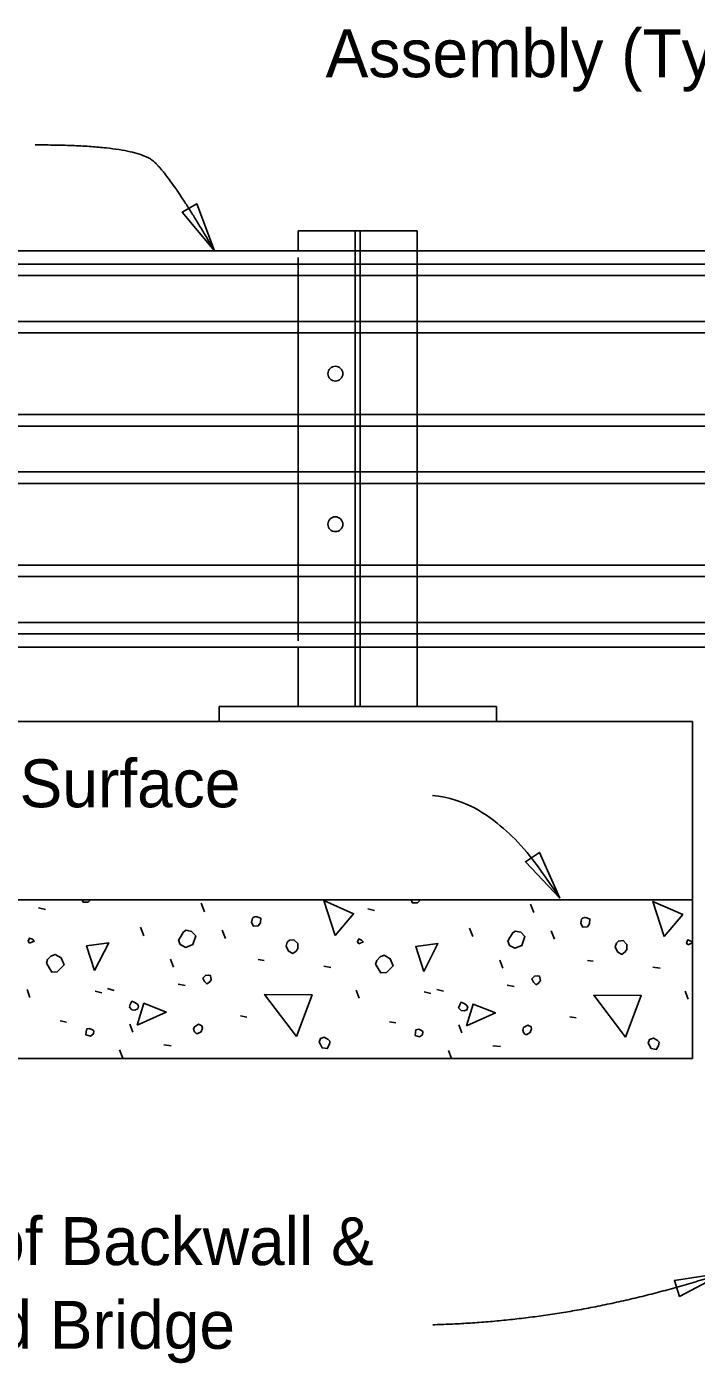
# Model space of a CAD drawing. Extents: x 21587 to 21659.1, y 56116.2 to 56157.3.
# Drawn here: x 21610.68 to 21613.5, y 56132.1 to 56137.72 of the extents above; entities that cross this region are included whole.
import ezdxf

# ---------------------------------------------------------------- set-up
doc = ezdxf.new("R2010")
doc.units = 0
for name, color, linetype in [('AdhocPoint_dp', 7, 'Continuous'), ('Border', 7, 'Continuous'), ('Patterning', 7, 'Continuous'), ('PlotBorder_dp', 7, 'Continuous'), ('SheetBorder_dp', 7, 'Continuous'), ('TextMisc', 7, 'Continuous')]:
    doc.layers.add(name, color=color, linetype=linetype)

msp = doc.modelspace()

# ---------------------------------------------------------------- linework, layer by layer
at = {"layer": 'AdhocPoint_dp'}
for p, q in [((21607.3117, 56134.8009), (21613.4854, 56134.8009)), ((21613.4854, 56134.8008), (21613.4854, 56133.3842)), ((21613.4854, 56134.0509), (21607.3117, 56134.0509)), ((21607.3117, 56133.3843), (21613.4854, 56133.3843))]:
    msp.add_line(p, q, dxfattribs=at)
at = {"layer": 'Border'}
for p, q in [((21611.8268, 56136.8635), (21612.3268, 56136.8635)), ((21611.8268, 56136.8635), (21611.8268, 56136.7802)), ((21612.3268, 56136.8635), (21612.3268, 56136.7802)), ((21619.5663, 56136.7801), (21607.3117, 56136.7801)), ((21607.3117, 56136.7246), (21619.5663, 56136.7246)), ((21607.3117, 56136.6764), (21619.5663, 56136.6764)), ((21607.3117, 56136.4835), (21619.5663, 56136.4835)), ((21607.3117, 56136.4353), (21619.5663, 56136.4353)), ((21607.3117, 56136.0914), (21619.5663, 56136.0914)), ((21607.3117, 56136.0431), (21619.5663, 56136.0431)), ((21607.3117, 56135.8503), (21619.5663, 56135.8503)), ((21607.3117, 56135.8022), (21619.5663, 56135.8022)), ((21607.3117, 56135.4582), (21619.5663, 56135.4582)), ((21607.3117, 56135.41), (21619.5663, 56135.41)), ((21607.3117, 56135.2172), (21619.5663, 56135.2172)), ((21607.3117, 56135.169), (21619.5663, 56135.169)), ((21619.5663, 56135.1134), (21607.3117, 56135.1134)), ((21611.8268, 56135.1135), (21611.8268, 56134.8635)), ((21612.3268, 56135.1134), (21612.3268, 56134.8635)), ((21611.4935, 56134.8635), (21612.6601, 56134.8635)), ((21611.4935, 56134.801), (21611.4935, 56134.8635)), ((21611.8268, 56134.8635), (21612.3268, 56134.8635)), ((21612.6601, 56134.8635), (21612.6601, 56134.801)), ((21611.4935, 56134.801), (21612.6601, 56134.801))]:
    msp.add_line(p, q, dxfattribs=at)
for centre in [(21611.983, 56136.2634), (21611.983, 56135.6303)]:
    msp.add_circle(centre, 0.0312, dxfattribs=at)
at = {"layer": 'Patterning'}
for p, q in [((21612.0664, 56134.8635), (21612.0664, 56136.8635)), ((21612.0872, 56134.8635), (21612.0872, 56136.8635)), ((21611.8268, 56136.7516), (21611.8268, 56135.1398)), ((21612.3268, 56136.7801), (21612.3268, 56135.1134))]:
    msp.add_line(p, q, dxfattribs=at)
at = {"layer": 'PlotBorder_dp'}
for points in [[(21611.474, 56136.7801), (21611.3998, 56136.9779), (21611.3388, 56136.9424)], [(21612.9278, 56134.0576), (21612.8414, 56134.2503), (21612.7827, 56134.211)], [(21613.6179, 56132.4823), (21613.4091, 56132.4504), (21613.4313, 56132.3834)]]:
    msp.add_lwpolyline(points, close=True, dxfattribs=at)
for points, degree in [([(21610.7197, 56137.2255), (21611.1414, 56137.2255), (21611.2961, 56137.086), (21611.474, 56136.7801)], 2), ([(21612.391, 56134.4896), (21612.5328, 56134.4753), (21612.7097, 56134.3451), (21612.8071, 56134.2379), (21612.9278, 56134.0575)], 3), ([(21613.6179, 56132.4823), (21613.0052, 56132.2796), (21612.3926, 56132.264)], 2)]:
    msp.add_open_spline(points, degree=degree, dxfattribs=at)
at = {"layer": 'TextMisc'}
for p, q in [((21610.7346, 56134.0167), (21610.7629, 56134.0096)), ((21611.4329, 56134.0008), (21611.4187, 56134.0362)), ((21612.1193, 56134.0132), (21612.1476, 56134.0061)), ((21612.8175, 56133.9973), (21612.8034, 56134.0326)), ((21611.1765, 56133.9), (21611.1624, 56133.9354)), ((21612.5612, 56133.8965), (21612.5471, 56133.9319)), ((21611.5206, 56133.8883), (21611.5065, 56133.9237)), ((21612.9053, 56133.8848), (21612.8912, 56133.9201)), ((21611.302, 56133.7675), (21611.2897, 56133.801)), ((21611.6585, 56133.7999), (21611.6833, 56133.7964)), ((21611.9343, 56133.7716), (21611.9643, 56133.7663)), ((21612.6867, 56133.7639), (21612.6743, 56133.7975)), ((21613.0432, 56133.7964), (21613.0679, 56133.7928)), ((21613.319, 56133.7681), (21613.349, 56133.7628)), ((21610.6981, 56133.6408), (21610.6857, 56133.6744)), ((21610.9721, 56133.6673), (21611.0004, 56133.6603)), ((21611.0245, 56133.6773), (21611.0528, 56133.6702)), ((21611.3209, 56133.6956), (21611.3509, 56133.6903)), ((21612.0828, 56133.6373), (21612.0704, 56133.6709)), ((21612.3568, 56133.6638), (21612.3851, 56133.6567)), ((21612.4092, 56133.6738), (21612.4375, 56133.6667)), ((21612.7055, 56133.6921), (21612.7356, 56133.6868)), ((21613.4674, 56133.6337), (21613.4551, 56133.6673)), ((21610.8254, 56133.5418), (21610.8519, 56133.5365)), ((21611.5843, 56133.563), (21611.6108, 56133.5577)), ((21612.21, 56133.5383), (21612.2366, 56133.533)), ((21612.9689, 56133.5595), (21612.9955, 56133.5542)), ((21611.1306, 56133.4947), (21611.1182, 56133.5283)), ((21612.5152, 56133.4912), (21612.5029, 56133.5248)), ((21611.0881, 56133.3851), (21611.074, 56133.4205)), ((21611.2608, 56133.4411), (21611.2926, 56133.4375)), ((21612.6454, 56133.4375), (21612.6773, 56133.434)), ((21612.4717, 56133.3843), (21612.4587, 56133.4169))]:
    msp.add_line(p, q, dxfattribs=at)
for points in [[(21610.9179, 56134.0509), (21610.922, 56134.0415), (21610.9184, 56134.045)], [(21610.922, 56134.0415), (21610.9432, 56134.0415), (21610.9527, 56134.0509)], [(21611.982, 56133.9007), (21611.9343, 56134.0474), (21612.0598, 56133.9926), (21611.982, 56133.9007)], [(21612.3017, 56134.0509), (21612.3013, 56134.0503), (21612.3067, 56134.0379), (21612.3031, 56134.0415)], [(21612.3067, 56134.0379), (21612.3279, 56134.0379), (21612.3385, 56134.0485), (21612.3378, 56134.0509)], [(21613.3667, 56133.8971), (21613.319, 56134.0439), (21613.4445, 56133.9891), (21613.3667, 56133.8971)], [(21611.6302, 56133.9555), (21611.6391, 56133.9396), (21611.6585, 56133.9413), (21611.6673, 56133.9537), (21611.6691, 56133.9731), (21611.6567, 56133.9785), (21611.6479, 56133.9802), (21611.6373, 56133.9767), (21611.6338, 56133.9731), (21611.6302, 56133.9555)], [(21613.0149, 56133.9519), (21613.0237, 56133.936), (21613.0432, 56133.9378), (21613.052, 56133.9502), (21613.0538, 56133.9696), (21613.0414, 56133.9749), (21613.0326, 56133.9767), (21613.022, 56133.9731), (21613.0184, 56133.9696), (21613.0149, 56133.9519)], [(21610.6963, 56133.8689), (21610.7158, 56133.8777), (21610.7087, 56133.8848), (21610.6963, 56133.8901), (21610.691, 56133.8777), (21610.6963, 56133.8689)], [(21610.9697, 56133.7533), (21610.9361, 56133.8576), (21611.0298, 56133.87), (21610.9697, 56133.7533)], [(21611.3303, 56133.8629), (21611.3533, 56133.8505), (21611.3834, 56133.8629), (21611.3957, 56133.9), (21611.3781, 56133.9177), (21611.3551, 56133.923), (21611.3445, 56133.916), (21611.3321, 56133.8965), (21611.3233, 56133.8806), (21611.3303, 56133.8629)], [(21611.7752, 56133.8565), (21611.7858, 56133.8353), (21611.8035, 56133.8247), (21611.8176, 56133.8353), (21611.8247, 56133.8459), (21611.8247, 56133.8671), (21611.8088, 56133.883), (21611.7893, 56133.8812), (21611.7805, 56133.8724), (21611.7752, 56133.8565)], [(21612.081, 56133.8653), (21612.1004, 56133.8742), (21612.0934, 56133.8812), (21612.081, 56133.8865), (21612.0757, 56133.8742), (21612.081, 56133.8653)], [(21612.715, 56133.8594), (21612.738, 56133.847), (21612.768, 56133.8594), (21612.7804, 56133.8965), (21612.7627, 56133.9142), (21612.7398, 56133.9195), (21612.7291, 56133.9124), (21612.7168, 56133.893), (21612.7079, 56133.8771), (21612.715, 56133.8594)], [(21613.1599, 56133.8529), (21613.1705, 56133.8317), (21613.1881, 56133.8211), (21613.2023, 56133.8317), (21613.2094, 56133.8423), (21613.2094, 56133.8635), (21613.1934, 56133.8795), (21613.174, 56133.8777), (21613.1652, 56133.8689), (21613.1599, 56133.8529)], [(21613.4657, 56133.8618), (21613.4851, 56133.8706), (21613.4781, 56133.8777), (21613.4657, 56133.883), (21613.4604, 56133.8706), (21613.4657, 56133.8618)], [(21610.767, 56133.784), (21610.79, 56133.7469), (21610.813, 56133.7486), (21610.8218, 56133.7575), (21610.8413, 56133.7769), (21610.8289, 56133.807), (21610.8042, 56133.8211), (21610.7865, 56133.814), (21610.7723, 56133.7999), (21610.767, 56133.784)], [(21612.1517, 56133.7805), (21612.1747, 56133.7433), (21612.1977, 56133.7451), (21612.2065, 56133.7539), (21612.226, 56133.7734), (21612.2136, 56133.8034), (21612.1888, 56133.8176), (21612.1712, 56133.8105), (21612.157, 56133.7964), (21612.1517, 56133.7805)], [(21612.3544, 56133.7498), (21612.3208, 56133.8541), (21612.4145, 56133.8665), (21612.3544, 56133.7498)], [(21611.4322, 56133.708), (21611.4428, 56133.6974), (21611.4534, 56133.7044), (21611.4605, 56133.7151), (21611.457, 56133.7327), (21611.4481, 56133.7345), (21611.4358, 56133.7327), (21611.4252, 56133.7221), (21611.4322, 56133.708)], [(21612.8169, 56133.7044), (21612.8275, 56133.6938), (21612.8381, 56133.7009), (21612.8452, 56133.7115), (21612.8417, 56133.7292), (21612.8328, 56133.731), (21612.8204, 56133.7292), (21612.8098, 56133.7186), (21612.8169, 56133.7044)], [(21611.8194, 56133.4764), (21611.685, 56133.6532), (21611.8848, 56133.6514), (21611.8194, 56133.4764)], [(21613.2041, 56133.4729), (21613.0697, 56133.6496), (21613.2695, 56133.6479), (21613.2041, 56133.4729)], [(21611.127, 56133.5889), (21611.1394, 56133.5871), (21611.1518, 56133.5925), (21611.1553, 56133.6031), (21611.15, 56133.6119), (21611.1394, 56133.619), (21611.127, 56133.6243), (21611.12, 56133.6101), (21611.1164, 56133.5995), (21611.127, 56133.5889)], [(21611.1494, 56133.5241), (21611.1777, 56133.6161), (21611.2714, 56133.5789), (21611.1494, 56133.5241)], [(21612.5117, 56133.5854), (21612.5241, 56133.5836), (21612.5365, 56133.5889), (21612.54, 56133.5995), (21612.5347, 56133.6084), (21612.5241, 56133.6154), (21612.5117, 56133.6207), (21612.5046, 56133.6066), (21612.5011, 56133.596), (21612.5117, 56133.5854)], [(21612.5341, 56133.5206), (21612.5624, 56133.6125), (21612.656, 56133.5754), (21612.5341, 56133.5206)], [(21610.9332, 56133.4835), (21610.9527, 56133.4782), (21610.965, 56133.487), (21610.9668, 56133.4994), (21610.9633, 56133.5029), (21610.9491, 56133.51), (21610.9367, 56133.5082), (21610.935, 56133.4959), (21610.9332, 56133.4835)], [(21611.3969, 56133.4888), (21611.4039, 56133.4888), (21611.4181, 56133.4959), (21611.4234, 56133.5118), (21611.4216, 56133.5206), (21611.4075, 56133.5277), (21611.3898, 56133.5171), (21611.3863, 56133.5065), (21611.3898, 56133.4959), (21611.3969, 56133.4888)], [(21612.3179, 56133.4799), (21612.3373, 56133.4746), (21612.3497, 56133.4835), (21612.3515, 56133.4959), (21612.3479, 56133.4994), (21612.3338, 56133.5065), (21612.3214, 56133.5047), (21612.3197, 56133.4923), (21612.3179, 56133.4799)], [(21612.7816, 56133.4852), (21612.7886, 56133.4852), (21612.8028, 56133.4923), (21612.8081, 56133.5082), (21612.8063, 56133.5171), (21612.7922, 56133.5241), (21612.7745, 56133.5135), (21612.7709, 56133.5029), (21612.7745, 56133.4923), (21612.7816, 56133.4852)], [(21611.9184, 56133.4446), (21611.9272, 56133.4287), (21611.9484, 56133.4251), (21611.9573, 56133.4411), (21611.9608, 56133.4552), (21611.952, 56133.464), (21611.936, 56133.4729), (21611.9201, 56133.4676), (21611.9148, 56133.4517), (21611.9184, 56133.4446)], [(21613.303, 56133.4411), (21613.3119, 56133.4251), (21613.3331, 56133.4216), (21613.3419, 56133.4375), (21613.3455, 56133.4517), (21613.3366, 56133.4605), (21613.3207, 56133.4693), (21613.3048, 56133.464), (21613.2995, 56133.4481), (21613.303, 56133.4411)]]:
    msp.add_lwpolyline(points, dxfattribs=at)

# ---------------------------------------------------------------- texts
at = {"layer": 'PlotBorder_dp'}
for s, p in [('Assembly (Typ.)', (21611.9419, 56137.51)), ('Front Face of Backwall &', (21609.1479, 56132.5148)), ('Begin or End Bridge', (21609.1479, 56132.1628))]:
    msp.add_text(s, height=0.2016, dxfattribs=at).set_placement(p)
at = {"layer": 'SheetBorder_dp'}
msp.add_text('Final Riding Surface', height=0.2016, dxfattribs=at).set_placement((21609.1559, 56134.44))

doc.saveas('drawing.dxf')
